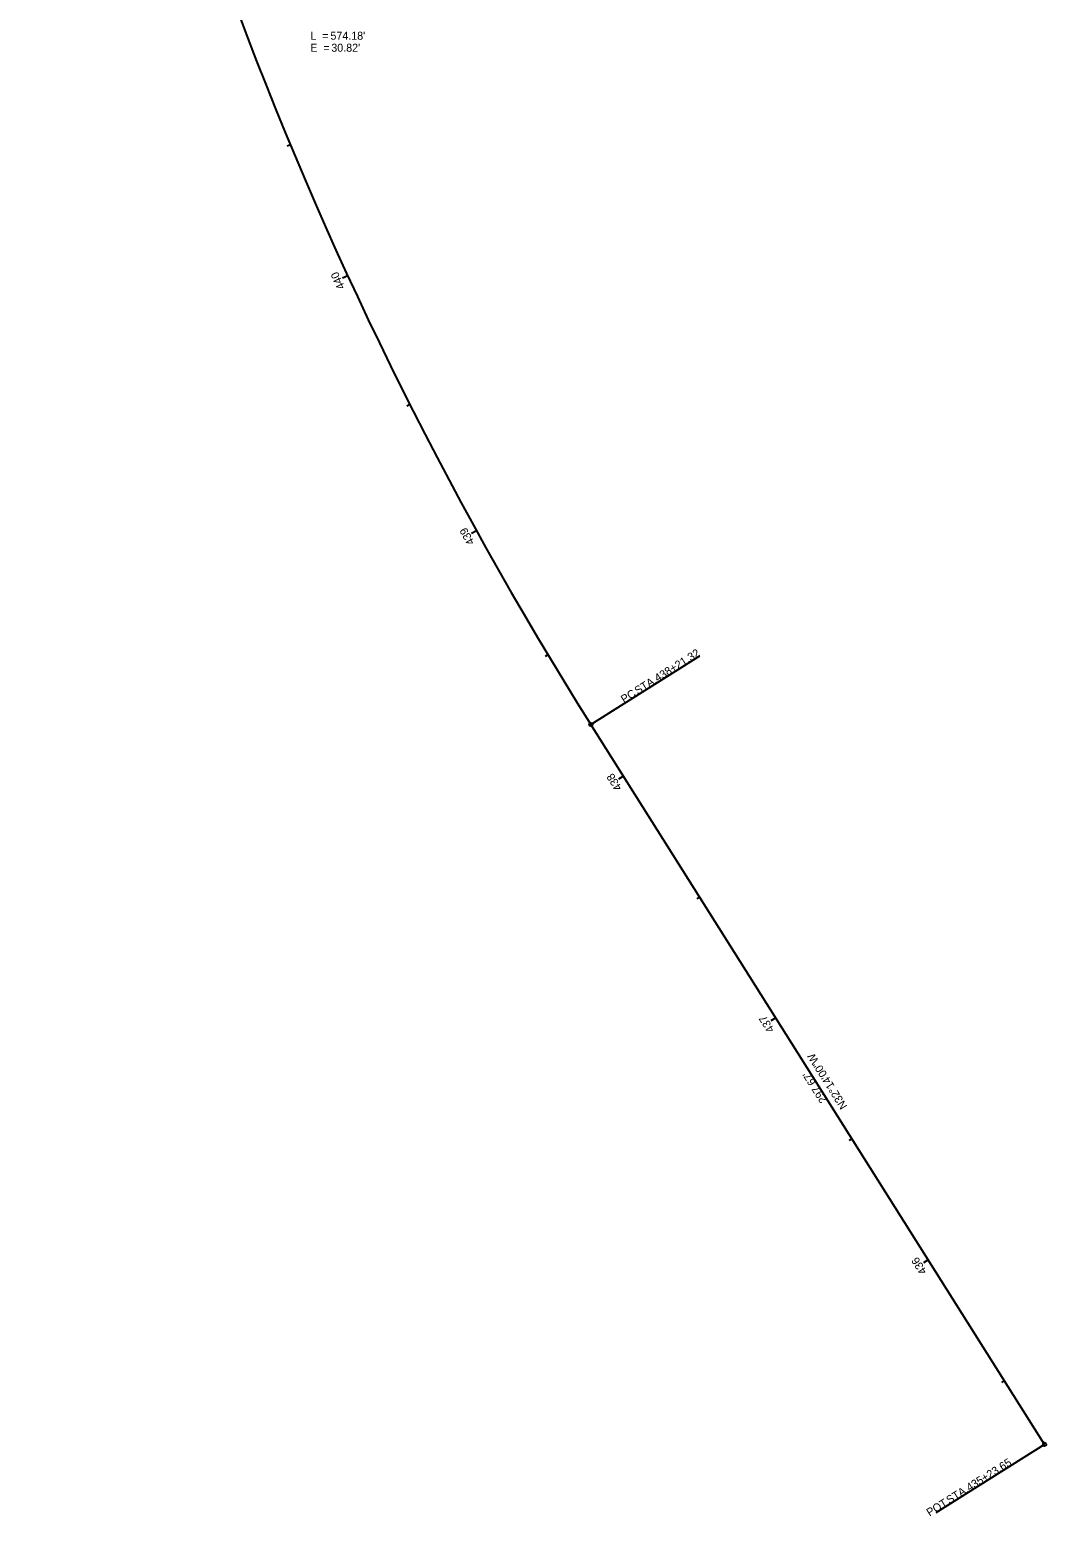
# Model space of a CAD drawing. Extents: x 124376 to 127490, y 510907 to 515083.
# Drawn here: x 127065 to 127421, y 510907 to 511427 of the extents above; entities that cross this region are included whole.
import ezdxf

# ---------------------------------------------------------------- set-up
doc = ezdxf.new("R2010")
doc.units = 0
for name, color, linetype in [('Default', 7, 'Continuous'), ('RW_X_CL', 7, 'Continuous'), ('RW_X_CL_100_Bearings', 7, 'Continuous'), ('RW_X_CL_100_Cardinal_Points', 7, 'Continuous'), ('RW_X_CL_100_Curve_Data', 7, 'Continuous'), ('RW_X_CL_100_Distances', 7, 'Continuous'), ('RW_X_CL_100_Stations', 7, 'Continuous')]:
    doc.layers.add(name, color=color, linetype=linetype)

msp = doc.modelspace()

# ---------------------------------------------------------------- linework, layer by layer
at = {"layer": 'Default'}
msp.add_line((127420, 510932.46), (127261.23, 511184.26), dxfattribs=at)
msp.add_arc((128413.54, 511910.84), 1362.26, 188.08366, 212.23338, dxfattribs=at)
at = {"layer": 'RW_X_CL'}
msp.add_line((127420, 510932.46), (127261.23, 511184.26), dxfattribs=at)
msp.add_arc((128413.54, 511910.84), 1362.26, 188.08366, 212.23338, dxfattribs=at)
at = {"layer": 'RW_X_CL_100_Cardinal_Points'}
for p, q in [((127261.23, 511184.26), (127299.29, 511208.26)), ((127420, 510932.46), (127381.93, 510908.46))]:
    msp.add_line(p, q, dxfattribs=at)
for centre in [(127261.23, 511184.26), (127420, 510932.46)]:
    msp.add_circle(centre, 0.6, dxfattribs=at)
at = {"layer": 'RW_X_CL_100_Stations'}
for p, q in [((127156.03, 511387), (127154.92, 511386.54)), ((127176.1, 511341.21), (127174.28, 511340.37)), ((127197.83, 511296.18), (127196.76, 511295.64)), ((127221.21, 511251.98), (127219.46, 511251.02)), ((127246.19, 511208.67), (127245.16, 511208.06)), ((127272.6, 511166.22), (127270.91, 511165.15)), ((127299.27, 511123.93), (127298.25, 511123.29)), ((127325.94, 511081.63), (127324.25, 511080.57)), ((127352.61, 511039.34), (127351.59, 511038.7)), ((127379.27, 510997.04), (127377.58, 510995.98)), ((127405.94, 510954.75), (127404.93, 510954.11))]:
    msp.add_line(p, q, dxfattribs=at)

# ---------------------------------------------------------------- texts
at = {"layer": 'RW_X_CL_100_Bearings'}
msp.add_text('N32°14\'00"W', height=2.8, rotation=122.2334, dxfattribs=at).set_placement((127351.09, 511050.74))
at = {"layer": 'RW_X_CL_100_Cardinal_Points'}
for s, p in [('438+21.32', (127284.59, 511199.03)), (' STA. ', (127276.71, 511194.06)), ('PC', (127272.81, 511191.6)), ('435+23.65', (127393.68, 510915.91)), ('POT', (127379.76, 510907.14)), (' STA. ', (127385.79, 510910.94))]:
    msp.add_text(s, height=2.8, rotation=32.2334, dxfattribs=at).set_placement(p)
at = {"layer": 'RW_X_CL_100_Curve_Data'}
for s, p in [('L  = ', (127163.02, 511423.77)), ('E  = ', (127163.02, 511419.57)), ("574.18'", (127170.06, 511423.77)), ("30.82'", (127170.37, 511419.57))]:
    msp.add_text(s, height=2.8, dxfattribs=at).set_placement(p)
at = {"layer": 'RW_X_CL_100_Distances'}
msp.add_text("297.67'", height=2.8, rotation=122.2334, dxfattribs=at).set_placement((127344.02, 511052.89))
at = {"layer": 'RW_X_CL_100_Stations'}
for s, rotation, p in [('440', 114.7182, (127175.19, 511337.19)), ('439', 118.9241, (127220.58, 511247.95)), ('438', 122.2334, (127272.22, 511162.14)), ('437', 122.2334, (127325.55, 511077.56)), ('436', 122.2334, (127378.9, 510992.96))]:
    msp.add_text(s, height=2.8, rotation=rotation, dxfattribs=at).set_placement(p)

doc.saveas('drawing.dxf')
